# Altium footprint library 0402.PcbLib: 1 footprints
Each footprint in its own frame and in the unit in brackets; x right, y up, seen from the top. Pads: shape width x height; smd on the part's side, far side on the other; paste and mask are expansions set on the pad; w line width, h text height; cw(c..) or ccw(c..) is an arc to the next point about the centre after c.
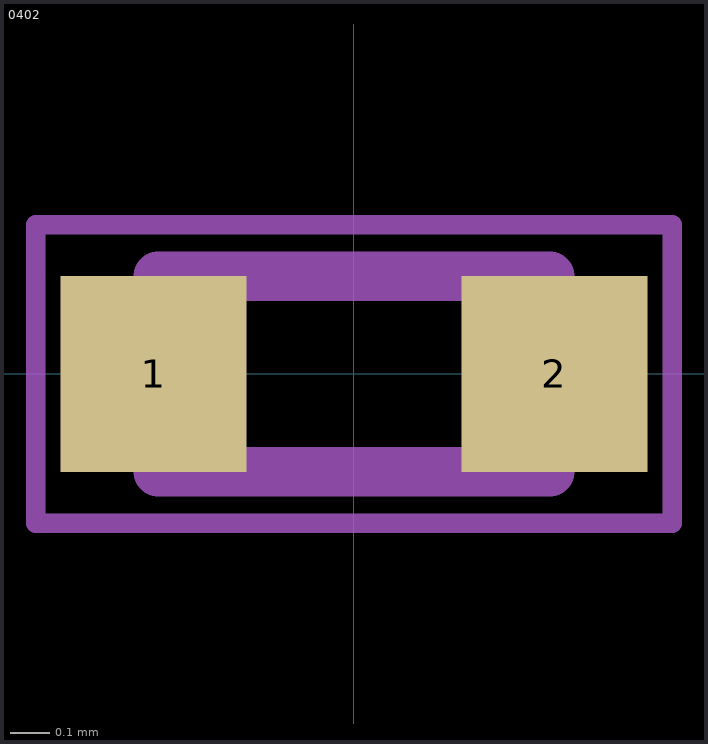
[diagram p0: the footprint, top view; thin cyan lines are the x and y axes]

## 0402 [mm]
height 0.35
pads (2):
  rect 0.475x0.5 smd: 1(-0.512,0) 2(0.512,0)
Assembly Top:
  lines w0.127: -0.5,-0.25 -0.5,0.25 0.5,0.25 0.5,-0.25 -0.5,-0.25
Courtyard Top:
  lines w0.05: -0.813,-0.381 -0.813,0.381 0.813,0.381 0.813,-0.381 -0.813,-0.381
